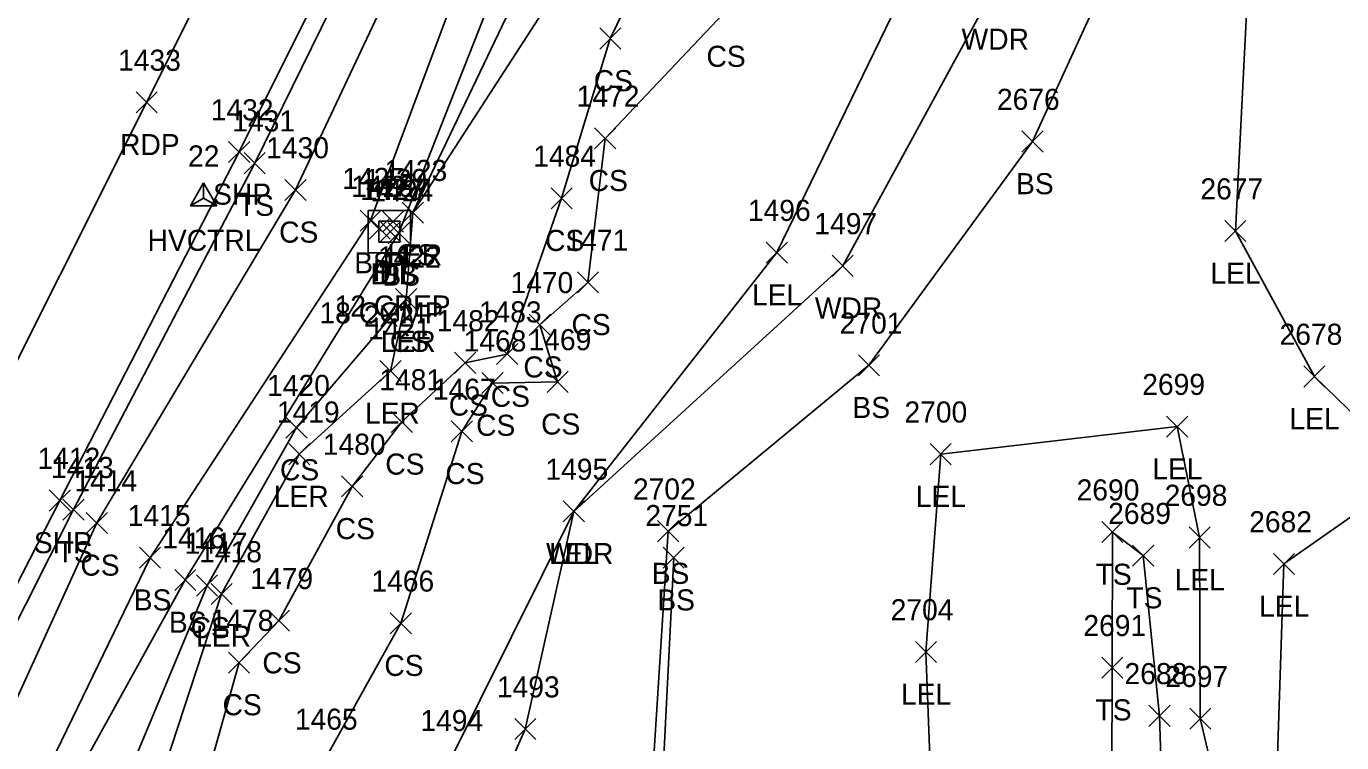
# Model space of a CAD drawing. Extents: x 1483143 to 1488182, y 802902 to 807581.
# Drawn here: x 1487503.2 to 1487627.8, y 805656.4 to 805724.4 of the extents above; entities that cross this region are included whole.
import ezdxf

# ---------------------------------------------------------------- set-up
doc = ezdxf.new("R2010")
doc.units = 0
for name, color, linetype in [('C_A', 7, 'Continuous'), ('C_I', 7, 'Continuous'), ('CPSM', 7, 'Continuous'), ('D_A', 7, 'Continuous'), ('D_C', 7, 'Continuous'), ('D_I', 7, 'Continuous'), ('D_TIC', 7, 'Continuous'), ('DS', 7, 'Continuous'), ('L_A', 7, 'Continuous'), ('L_I', 7, 'Continuous'), ('L_TIC', 7, 'Continuous'), ('LARO', 7, 'Continuous'), ('LAWA', 7, 'Continuous'), ('LELB', 7, 'Continuous'), ('P_A', 7, 'Continuous'), ('P_I', 7, 'Continuous'), ('P_TIC', 7, 'Continuous'), ('PET', 7, 'Continuous'), ('PSP', 7, 'Continuous')]:
    doc.layers.add(name, color=color, linetype=linetype)

msp = doc.modelspace()

# ---------------------------------------------------------------- linework, layer by layer
at = {"layer": 'CPSM'}
for p, q in [((1487518.72, 805707.35), (1487519.97, 805709.51)), ((1487521.22, 805707.35), (1487519.97, 805709.51)), ((1487519.97, 805708.07), (1487519.97, 805709.51)), ((1487518.72, 805707.35), (1487519.97, 805708.07)), ((1487518.72, 805707.35), (1487521.22, 805707.35)), ((1487519.97, 805708.07), (1487519.97, 805708.07)), ((1487519.97, 805708.07), (1487521.22, 805707.35))]:
    msp.add_line(p, q, dxfattribs=at)
at = {"layer": 'D_TIC'}
for points in [[(1487535.65, 805704.19), (1487537.65, 805706.19)], [(1487537.65, 805704.19), (1487535.65, 805706.19)], [(1487536.67, 805703.9), (1487538.67, 805705.9)], [(1487538.67, 805703.9), (1487536.67, 805705.9)], [(1487536.91, 805704.84), (1487538.91, 805706.84)], [(1487538.91, 805704.84), (1487536.91, 805706.84)]]:
    msp.add_lwpolyline(points, dxfattribs=at)
at = {"layer": 'DS'}
for p, q in [((1487535.57, 805706.89), (1487539.57, 805706.89)), ((1487535.57, 805702.89), (1487535.57, 805706.89)), ((1487536.57, 805703.89), (1487536.57, 805705.89)), ((1487536.57, 805705.89), (1487538.57, 805705.89)), ((1487538.57, 805705.89), (1487538.57, 805703.89)), ((1487539.57, 805706.89), (1487539.57, 805702.89)), ((1487537.57, 805704.89), (1487537.57, 805704.89)), ((1487537.57, 805704.89), (1487537.57, 805704.89)), ((1487538.57, 805703.89), (1487536.57, 805703.89)), ((1487539.57, 805702.89), (1487535.57, 805702.89))]:
    msp.add_line(p, q, dxfattribs=at)
at = {"layer": 'L_TIC'}
for points in [[(1487557.5, 805722.21), (1487559.5, 805724.21)], [(1487559.5, 805722.21), (1487557.5, 805724.21)], [(1487557.02, 805712.74), (1487559.02, 805714.74)], [(1487559.02, 805712.74), (1487557.02, 805714.74)], [(1487597.51, 805712.44), (1487599.51, 805714.44)], [(1487599.51, 805712.44), (1487597.51, 805714.44)], [(1487523.82, 805710.39), (1487525.82, 805712.39)], [(1487525.82, 805710.39), (1487523.82, 805712.39)], [(1487527.68, 805707.85), (1487529.68, 805709.85)], [(1487529.68, 805707.85), (1487527.68, 805709.85)], [(1487552.89, 805707.06), (1487554.89, 805709.06)], [(1487554.89, 805707.06), (1487552.89, 805709.06)], [(1487534.8, 805704.94), (1487536.8, 805706.94)], [(1487536.8, 805704.94), (1487534.8, 805706.94)], [(1487538.8, 805705.7), (1487540.8, 805707.7)], [(1487540.8, 805705.7), (1487538.8, 805707.7)], [(1487538.8, 805705.7), (1487540.8, 805707.7)], [(1487540.8, 805705.7), (1487538.8, 805707.7)], [(1487537.47, 805703.77), (1487539.47, 805705.77)], [(1487539.47, 805703.77), (1487537.47, 805705.77)], [(1487616.73, 805703.95), (1487618.73, 805705.95)], [(1487618.73, 805703.95), (1487616.73, 805705.95)], [(1487573.29, 805701.91), (1487575.29, 805703.91)], [(1487575.29, 805701.91), (1487573.29, 805703.91)], [(1487579.53, 805700.65), (1487581.53, 805702.65)], [(1487581.53, 805700.65), (1487579.53, 805702.65)], [(1487555.39, 805699.08), (1487557.39, 805701.08)], [(1487557.39, 805699.08), (1487555.39, 805701.08)], [(1487538.17, 805697.49), (1487540.17, 805699.49)], [(1487540.17, 805697.49), (1487538.17, 805699.49)], [(1487538.17, 805697.49), (1487540.17, 805699.49)], [(1487540.17, 805697.49), (1487538.17, 805699.49)], [(1487550.83, 805695.06), (1487552.83, 805697.06)], [(1487552.83, 805695.06), (1487550.83, 805697.06)], [(1487543.76, 805691.45), (1487545.76, 805693.45)], [(1487545.76, 805691.45), (1487543.76, 805693.45)], [(1487547.74, 805692.28), (1487549.74, 805694.28)], [(1487549.74, 805692.28), (1487547.74, 805694.28)], [(1487582.01, 805691.22), (1487584.01, 805693.22)], [(1487584.01, 805691.22), (1487582.01, 805693.22)], [(1487536.68, 805690.67), (1487538.68, 805692.67)], [(1487538.68, 805690.67), (1487536.68, 805692.67)], [(1487624.22, 805690.16), (1487626.22, 805692.16)], [(1487626.22, 805690.16), (1487624.22, 805692.16)], [(1487546.35, 805689.53), (1487548.35, 805691.53)], [(1487548.35, 805689.53), (1487546.35, 805691.53)], [(1487552.51, 805689.65), (1487554.51, 805691.65)], [(1487554.51, 805689.65), (1487552.51, 805691.65)], [(1487527.77, 805685.31), (1487529.77, 805687.31)], [(1487529.77, 805685.31), (1487527.77, 805687.31)], [(1487537.75, 805685.85), (1487539.75, 805687.85)], [(1487539.75, 805685.85), (1487537.75, 805687.85)], [(1487611.22, 805685.41), (1487613.22, 805687.41)], [(1487613.22, 805685.41), (1487611.22, 805687.41)], [(1487543.44, 805684.95), (1487545.44, 805686.95)], [(1487545.44, 805684.95), (1487543.44, 805686.95)], [(1487528.04, 805682.79), (1487530.04, 805684.79)], [(1487530.04, 805682.79), (1487528.04, 805684.79)], [(1487588.81, 805682.79), (1487590.81, 805684.79)], [(1487590.81, 805682.79), (1487588.81, 805684.79)], [(1487533.05, 805679.73), (1487535.05, 805681.73)], [(1487535.05, 805679.73), (1487533.05, 805681.73)], [(1487506.64, 805677.53), (1487508.64, 805679.53)], [(1487508.64, 805677.53), (1487506.64, 805679.53)], [(1487508.86, 805676.27), (1487510.86, 805678.27)], [(1487510.86, 805676.27), (1487508.86, 805678.27)], [(1487554.05, 805677.36), (1487556.05, 805679.36)], [(1487556.05, 805677.36), (1487554.05, 805679.36)], [(1487554.05, 805677.36), (1487556.05, 805679.36)], [(1487556.05, 805677.36), (1487554.05, 805679.36)], [(1487562.99, 805675.49), (1487564.99, 805677.49)], [(1487564.99, 805675.49), (1487562.99, 805677.49)], [(1487605.08, 805675.4), (1487607.08, 805677.4)], [(1487607.08, 805675.4), (1487605.08, 805677.4)], [(1487613.34, 805674.89), (1487615.34, 805676.89)], [(1487615.34, 805674.89), (1487613.34, 805676.89)], [(1487513.9, 805672.97), (1487515.9, 805674.97)], [(1487515.9, 805672.97), (1487513.9, 805674.97)], [(1487563.52, 805672.97), (1487565.52, 805674.97)], [(1487565.52, 805672.97), (1487563.52, 805674.97)], [(1487608, 805673.17), (1487610, 805675.17)], [(1487610, 805673.17), (1487608, 805675.17)], [(1487621.34, 805672.38), (1487623.34, 805674.38)], [(1487623.34, 805672.38), (1487621.34, 805674.38)], [(1487517.24, 805670.86), (1487519.24, 805672.86)], [(1487519.24, 805670.86), (1487517.24, 805672.86)], [(1487519.3, 805670.34), (1487521.3, 805672.34)], [(1487521.3, 805670.34), (1487519.3, 805672.34)], [(1487520.68, 805669.54), (1487522.68, 805671.54)], [(1487522.68, 805669.54), (1487520.68, 805671.54)], [(1487526.1, 805667), (1487528.1, 805669)], [(1487528.1, 805667), (1487526.1, 805669)], [(1487537.66, 805666.76), (1487539.66, 805668.76)], [(1487539.66, 805666.76), (1487537.66, 805668.76)], [(1487587.41, 805664.04), (1487589.41, 805666.04)], [(1487589.41, 805664.04), (1487587.41, 805666.04)], [(1487522.33, 805663.03), (1487524.33, 805665.03)], [(1487524.33, 805663.03), (1487522.33, 805665.03)], [(1487605.07, 805662.54), (1487607.07, 805664.54)], [(1487607.07, 805662.54), (1487605.07, 805664.54)], [(1487609.54, 805657.98), (1487611.54, 805659.98)], [(1487611.54, 805657.98), (1487609.54, 805659.98)], [(1487613.41, 805657.71), (1487615.41, 805659.71)], [(1487615.41, 805657.71), (1487613.41, 805659.71)], [(1487549.45, 805656.72), (1487551.45, 805658.72)], [(1487551.45, 805656.72), (1487549.45, 805658.72)]]:
    msp.add_lwpolyline(points, dxfattribs=at)
at = {"layer": 'LARO'}
for points in [[(1487519.52, 805604.85), (1487528.65, 805619.18), (1487533.33, 805631.91), (1487543.2, 805654.53), (1487555.05, 805678.36), (1487574.29, 805702.91), (1487587.86, 805730.92), (1487594.38, 805745.99), (1487602.81, 805747.66), (1487615.34, 805754.21), (1487619.89, 805765.57), (1487618.06, 805788.02), (1487632.01, 805808.09), (1487647.52, 805827.2), (1487662.05, 805847.87), (1487673.84, 805865.59), (1487680.96, 805879.63), (1487690.31, 805890.08), (1487695.82, 805899.7), (1487708.05, 805917.66), (1487714.11, 805946.66), (1487707.45, 805965.6), (1487711.43, 805989.94)], [(1487515.16, 805650.67), (1487521.68, 805670.54), (1487529.04, 805683.79), (1487537.68, 805691.67), (1487539.17, 805698.49), (1487539.8, 805706.7), (1487559.66, 805737.44), (1487565.81, 805755.37), (1487573.16, 805761.97), (1487578.75, 805774.48), (1487583.53, 805786.84), (1487609.69, 805840.26), (1487624.13, 805853.53), (1487644.16, 805893.39), (1487661.53, 805944.93), (1487666.95, 805964.97), (1487680.31, 805984.75)], [(1487705.29, 805896.34), (1487695.87, 805891.2), (1487689.13, 805878.29), (1487689.57, 805859.67), (1487670.44, 805829.21), (1487659.71, 805823.79), (1487649.08, 805803.93), (1487638.97, 805785.42), (1487633.21, 805776.22), (1487626.14, 805756.53), (1487619.37, 805736.85), (1487617.73, 805704.95), (1487625.22, 805691.16), (1487634.64, 805682.02), (1487622.34, 805673.38), (1487621.2, 805638.86), (1487621.06, 805617.78)], [(1487610.84, 805619.03), (1487616.21, 805651.1), (1487614.41, 805658.71), (1487614.34, 805675.89), (1487612.22, 805686.41), (1487589.81, 805683.79), (1487588.41, 805665.04), (1487589.09, 805646.88), (1487587.23, 805619.42), (1487592.18, 805594.63), (1487596.26, 805581.06)]]:
    msp.add_lwpolyline(points, dxfattribs=at)
at = {"layer": 'LAWA'}
msp.add_lwpolyline([(1487529.09, 805606.14), (1487539.28, 805632.42), (1487550.45, 805657.72), (1487555.05, 805678.36), (1487580.53, 805701.65), (1487594.42, 805727.14), (1487615.34, 805754.21), (1487623.26, 805766.5), (1487630.87, 805783.06), (1487637.96, 805804.22), (1487654.61, 805825.46), (1487661.73, 805840.49), (1487675.69, 805864.29), (1487683.26, 805876.52), (1487690.31, 805890.08), (1487698.57, 805894.98), (1487712.71, 805915.11), (1487715.76, 805935.97), (1487722.85, 805947.47), (1487721.66, 805955.35), (1487715.74, 805966.94), (1487726.15, 805982.46)], dxfattribs=at)
at = {"layer": 'LELB'}
for points in [[(1487406.66, 805485.41), (1487431.45, 805531.24), (1487454.84, 805575.74), (1487473.75, 805612.05), (1487489.43, 805642.37), (1487507.64, 805678.53), (1487524.82, 805711.39), (1487541.86, 805746.09), (1487557.67, 805776.44), (1487575.49, 805812.01), (1487597.52, 805857.93), (1487620.62, 805906.82), (1487641.85, 805951.94), (1487662.18, 805996.35), (1487684.09, 806043.93), (1487694.42, 806066.95), (1487726.58, 806140.7), (1487745.85, 806185.55), (1487769.04, 806237.65), (1487788.58, 806284.85), (1487808.3, 806333.26), (1487827.52, 806379.6), (1487850.09, 806437.73)], [(1487410.04, 805483.24), (1487436.07, 805529.53), (1487459.78, 805575.03), (1487477.42, 805609.67), (1487492.45, 805639.09), (1487509.86, 805677.27), (1487528.68, 805708.85), (1487545.3, 805744.17), (1487561.79, 805774.32), (1487579.7, 805810.21), (1487602.04, 805856.31), (1487624.97, 805905.57), (1487645.72, 805950.02), (1487667.21, 805993.1), (1487687.16, 806043.23), (1487699.2, 806065.16), (1487730.65, 806138.87), (1487749.96, 806183.58), (1487772.93, 806235.17), (1487792.36, 806283.08), (1487812.9, 806331.5), (1487831.61, 806378.23), (1487855.61, 806436.65)], [(1487413.83, 805481.53), (1487440.22, 805526.89), (1487464.36, 805572.85), (1487481.71, 805606.55), (1487496.63, 805636.25), (1487514.9, 805673.97), (1487535.8, 805705.94), (1487549.07, 805741.59), (1487566.17, 805772.22), (1487583.99, 805807.69), (1487605.26, 805855.28), (1487629.33, 805903.01), (1487650.26, 805948.76), (1487670.48, 805991.25), (1487690.28, 806041.74), (1487702.22, 806061.37), (1487704.47, 806066.39), (1487735.28, 806136.71), (1487754, 806182.42), (1487776.55, 806233.47), (1487796.75, 806281.41), (1487816.88, 806330.25), (1487835.19, 806376.59), (1487859.78, 806434.97)], [(1487417, 805480.8), (1487442.28, 805525.8), (1487466.47, 805571.82), (1487483.84, 805604.86), (1487498.25, 805635.76), (1487518.24, 805671.86), (1487538.47, 805704.77), (1487552.2, 805739.67), (1487568.17, 805771.84), (1487585.97, 805806.76), (1487609.39, 805853.47), (1487632.34, 805900.81), (1487653.02, 805947.32), (1487672.59, 805990.01), (1487694.92, 806039.27), (1487707.45, 806059.25), (1487710.05, 806064.3), (1487737.97, 806135.43), (1487757.4, 806181.42), (1487778.76, 806231.94), (1487799.97, 806279.97), (1487818.92, 806329.91), (1487837.5, 806376), (1487863.45, 806433.38)], [(1487539.8, 805706.7), (1487554.99, 805738.51), (1487564.78, 805761.24), (1487572.42, 805770.06), (1487590.42, 805804.18), (1487613.31, 805851.36), (1487639.64, 805896.3), (1487657.07, 805945.9), (1487666.95, 805964.97), (1487675.89, 805987.99), (1487698.82, 806037.9), (1487713.56, 806059.8), (1487740.03, 806134.78), (1487759.8, 806179.98), (1487782.43, 806230.23), (1487804.48, 806278.55), (1487821.45, 806329.34), (1487839.66, 806374.66), (1487865.87, 806433.14)], [(1487428.48, 805479.23), (1487445.24, 805504.83), (1487451, 805517.25), (1487457.88, 805528.42), (1487471.74, 805554.31), (1487483.64, 805581.5), (1487492.13, 805596.22), (1487504.57, 805614.88), (1487515.61, 805636.44), (1487523.33, 805664.03), (1487527.1, 805668), (1487534.05, 805680.73), (1487538.75, 805686.85), (1487544.76, 805692.45), (1487548.74, 805693.28), (1487553.89, 805708.06), (1487558.5, 805723.21), (1487562.96, 805732.39), (1487569.7, 805746.23), (1487572.43, 805748.36), (1487588.97, 805765.58), (1487591.12, 805760.32), (1487603.32, 805759.56)], [(1487438.06, 805486.56), (1487449.51, 805502.69), (1487463.77, 805527.56), (1487473.75, 805548.89), (1487480.23, 805555.64), (1487489.68, 805553.31), (1487531.36, 805654.66), (1487538.66, 805667.76), (1487544.44, 805685.95), (1487547.35, 805690.53), (1487553.51, 805690.65), (1487551.83, 805696.06), (1487556.39, 805700.08), (1487558.02, 805713.74), (1487569.17, 805725.52), (1487574.82, 805736.37), (1487607.32, 805758.13)], [(1487626.14, 805756.53), (1487608.58, 805735.47), (1487598.51, 805713.44), (1487583.01, 805692.22), (1487563.99, 805676.49), (1487562.34, 805650.68)], [(1487199.3, 805080.96), (1487209.02, 805107.06), (1487224.53, 805127.21), (1487240.95, 805152.24), (1487249.95, 805171.94), (1487269.65, 805210.5), (1487285.86, 805237.33), (1487303.36, 805267.84), (1487322.25, 805302.17), (1487347.45, 805347.07), (1487376.58, 805390.13), (1487398.58, 805433.78), (1487419.88, 805479.75), (1487445.41, 805524.09), (1487470.45, 805569.86), (1487486.06, 805603.16), (1487492.1, 805615.56), (1487500.68, 805632.42), (1487507.33, 805640.17), (1487520.3, 805671.34), (1487528.77, 805686.31), (1487539.17, 805698.49)], [(1487606.56, 805621.21), (1487611.04, 805643.38), (1487610.54, 805658.98), (1487609, 805674.17), (1487606.08, 805676.4), (1487606.07, 805663.54), (1487606.01, 805642.84), (1487602.69, 805618.1), (1487601.76, 805602.01)], [(1487564.52, 805673.97), (1487563.22, 805648.26), (1487549.74, 805628.2), (1487535.27, 805607.28), (1487523.05, 805587.43), (1487520.1, 805562.54), (1487524.46, 805543.15), (1487523.95, 805516.73)]]:
    msp.add_lwpolyline(points, dxfattribs=at)
at = {"layer": 'P_TIC'}
for points in [[(1487513.57, 805716.15), (1487515.57, 805718.15)], [(1487515.57, 805716.15), (1487513.57, 805718.15)], [(1487522.34, 805711.45), (1487524.34, 805713.45)], [(1487524.34, 805711.45), (1487522.34, 805713.45)], [(1487505.35, 805678.4), (1487507.35, 805680.4)], [(1487507.35, 805678.4), (1487505.35, 805680.4)]]:
    msp.add_lwpolyline(points, dxfattribs=at)
at = {"layer": 'PET'}
msp.add_lwpolyline([(1487396.33, 805490.41), (1487421.9, 805537.94), (1487444.13, 805580.16), (1487464.29, 805618.83), (1487479.8, 805648.39), (1487498.08, 805684.27), (1487514.57, 805717.15), (1487530.55, 805749.06), (1487547.16, 805782.47), (1487564.33, 805817.54), (1487585.71, 805863.32), (1487608.89, 805911.38), (1487630.35, 805956.68), (1487651.22, 806001.25), (1487672.63, 806048.33), (1487683.65, 806072.29), (1487715.61, 806144.47), (1487735.35, 806190.47), (1487757.48, 806241.03), (1487777.65, 806289.15), (1487798.25, 806337.46), (1487817.05, 806384.04), (1487839.67, 806441.4)], dxfattribs=at)
at = {"layer": 'PSP'}
msp.add_lwpolyline([(1487405.03, 805486.21), (1487429.8, 805532.42), (1487452.92, 805576.31), (1487472.37, 805613.24), (1487487.86, 805643.29), (1487506.35, 805679.4), (1487523.34, 805712.45), (1487540.38, 805746.64), (1487556.03, 805777.85), (1487573.44, 805813.27), (1487595.34, 805859.04), (1487618.37, 805906.67), (1487640.09, 805952.42), (1487660.18, 805997.21), (1487682.38, 806044.71), (1487693.04, 806068.56), (1487725.12, 806141.19), (1487744.39, 806185.87), (1487766.81, 806238.55), (1487786.8, 806285.64), (1487806.77, 806333.93), (1487825.55, 806380.21), (1487847.81, 806437.56)], dxfattribs=at)

# ---------------------------------------------------------------- texts
at = {"layer": 'C_A'}
msp.add_text('HVCTRL', height=2, dxfattribs=at).set_placement((1487514.66, 805703.07))
at = {"layer": 'C_I'}
msp.add_text('22', height=2, dxfattribs=at).set_placement((1487518.5, 805711.07))
at = {"layer": 'D_A'}
for s, p in [('P', (1487536.03, 805700.19)), ('P', (1487537.29, 805700.84)), ('DIB', (1487535.77, 805699.9)), ('DI', (1487536.63, 805699.89))]:
    msp.add_text(s, height=2, dxfattribs=at).set_placement(p)
at = {"layer": 'D_C'}
for s, p in [('18 CGMP', (1487530.95, 805696.19)), ('12 CPEP', (1487532.38, 805696.84)), ('2X2', (1487535.15, 805695.89))]:
    msp.add_text(s, height=2, dxfattribs=at).set_placement(p)
at = {"layer": 'D_I'}
for s, p in [('1429', (1487535.21, 805708.84)), ('1428', (1487533.96, 805708.19)), ('1426', (1487534.82, 805707.89)), ('1427', (1487534.98, 805707.9))]:
    msp.add_text(s, height=2, dxfattribs=at).set_placement(p)
at = {"layer": 'L_A'}
for s, p in [('WDR', (1487591.79, 805722.14)), ('CS', (1487567.62, 805720.52)), ('CS', (1487556.94, 805718.21)), ('CS', (1487556.46, 805708.74)), ('BS', (1487596.95, 805708.44)), ('TS', (1487523.23, 805706.39)), ('CS', (1487527.13, 805703.85)), ('CS', (1487552.33, 805703.06)), ('LER', (1487537.38, 805701.7)), ('CS', (1487538.24, 805701.7)), ('BS', (1487534.24, 805700.94)), ('LEL', (1487615.37, 805699.95)), ('BS', (1487536.91, 805699.77)), ('LEL', (1487571.93, 805697.91)), ('WDR', (1487577.89, 805696.65)), ('CS', (1487554.83, 805695.08)), ('LER', (1487536.76, 805693.49)), ('CS', (1487537.62, 805693.49)), ('CS', (1487550.27, 805691.06)), ('CS', (1487547.18, 805688.28)), ('LER', (1487535.26, 805686.67)), ('CS', (1487543.2, 805687.45)), ('BS', (1487581.45, 805687.22)), ('CS', (1487545.79, 805685.53)), ('CS', (1487551.95, 805685.65)), ('LEL', (1487622.86, 805686.16)), ('CS', (1487527.21, 805681.31)), ('CS', (1487537.19, 805681.85)), ('LEL', (1487609.86, 805681.41)), ('CS', (1487542.88, 805680.95)), ('LER', (1487526.62, 805678.79)), ('LEL', (1487587.45, 805678.79)), ('CS', (1487532.49, 805675.73)), ('TS', (1487506.05, 805673.53)), ('WDR', (1487552.42, 805673.36)), ('LEL', (1487552.69, 805673.36)), ('CS', (1487508.3, 805672.27)), ('BS', (1487562.43, 805671.49)), ('TS', (1487604.49, 805671.4)), ('LEL', (1487611.98, 805670.89)), ('BS', (1487513.35, 805668.97)), ('BS', (1487562.96, 805668.97)), ('TS', (1487607.41, 805669.17)), ('LEL', (1487619.98, 805668.38)), ('BS', (1487516.68, 805666.86)), ('CS', (1487518.74, 805666.34)), ('LER', (1487519.26, 805665.54)), ('CS', (1487525.54, 805663)), ('CS', (1487537.1, 805662.76)), ('CS', (1487521.77, 805659.03)), ('LEL', (1487586.05, 805660.04)), ('TS', (1487604.48, 805658.54))]:
    msp.add_text(s, height=2, dxfattribs=at).set_placement(p)
at = {"layer": 'L_I'}
for s, p in [('1472', (1487555.32, 805716.74)), ('2676', (1487595.14, 805716.44)), ('1431', (1487522.69, 805714.39)), ('1430', (1487525.9, 805711.85)), ('1484', (1487551.2, 805711.06)), ('1425', (1487533.11, 805708.94)), ('1423', (1487537.11, 805709.7)), ('1423', (1487537.11, 805709.7)), ('1424', (1487535.78, 805707.77)), ('2677', (1487614.42, 805707.95)), ('1496', (1487571.54, 805705.91)), ('1497', (1487577.84, 805704.65)), ('1471', (1487554.26, 805703.08)), ('1422', (1487536.48, 805701.49)), ('1422', (1487536.48, 805701.49)), ('1470', (1487549.05, 805699.06)), ('1483', (1487546.05, 805696.28)), ('1482', (1487542.06, 805695.45)), ('2701', (1487580.24, 805695.22)), ('1421', (1487535.56, 805694.67)), ('2678', (1487621.92, 805694.16)), ('1468', (1487544.61, 805693.53)), ('1469', (1487550.76, 805693.65)), ('1420', (1487525.99, 805689.31)), ('1481', (1487536.62, 805689.85)), ('1467', (1487541.7, 805688.95)), ('2699', (1487608.91, 805689.41)), ('1419', (1487526.91, 805686.79)), ('2700', (1487586.38, 805686.79)), ('1480', (1487531.27, 805683.73)), ('1413', (1487505.51, 805681.53)), ('1495', (1487552.36, 805681.36)), ('1495', (1487552.36, 805681.36)), ('1414', (1487507.73, 805680.27)), ('2702', (1487560.65, 805679.49)), ('2690', (1487602.69, 805679.4)), ('2698', (1487611.03, 805678.89)), ('1415', (1487512.78, 805676.97)), ('2751', (1487561.83, 805676.97)), ('2689', (1487605.68, 805677.17)), ('2682', (1487619.04, 805676.38)), ('1416', (1487516.06, 805674.86)), ('1417', (1487518.17, 805674.34)), ('1418', (1487519.55, 805673.54)), ('1479', (1487524.4, 805671)), ('1466', (1487535.87, 805670.76)), ('2704', (1487585.07, 805668.04)), ('1478', (1487520.64, 805667.03)), ('2691', (1487603.33, 805666.54)), ('2688', (1487607.23, 805661.98)), ('2697', (1487611.1, 805661.71)), ('1493', (1487547.76, 805660.72)), ('1465', (1487528.62, 805657.66)), ('1494', (1487540.51, 805657.53))]:
    msp.add_text(s, height=2, dxfattribs=at).set_placement(p)
at = {"layer": 'P_A'}
for s, p in [('RDP', (1487512.06, 805712.15)), ('SHP', (1487520.87, 805707.45)), ('SHP', (1487503.89, 805674.4))]:
    msp.add_text(s, height=2, dxfattribs=at).set_placement(p)
at = {"layer": 'P_I'}
for s, p in [('1433', (1487511.87, 805720.15)), ('1432', (1487520.65, 805715.45)), ('1412', (1487504.23, 805682.4))]:
    msp.add_text(s, height=2, dxfattribs=at).set_placement(p)

doc.saveas('drawing.dxf')
